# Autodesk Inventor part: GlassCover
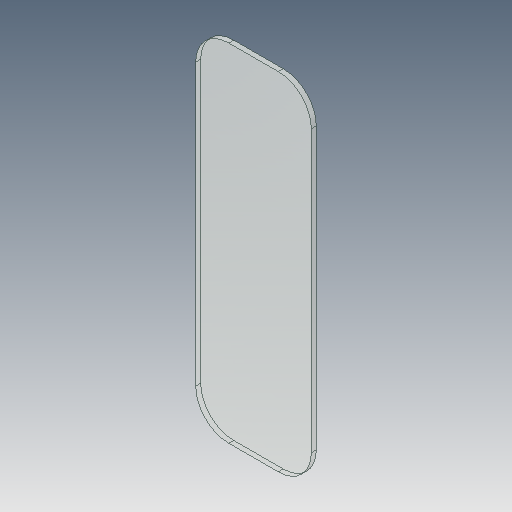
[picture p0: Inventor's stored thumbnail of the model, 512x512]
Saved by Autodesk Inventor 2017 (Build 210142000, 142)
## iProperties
Created: 2019-02
Part Number: GlassCover
Material: Glass
Document SubType Name: Modeling
Designer: user
Density: 2.18 g/cm^3
Appearance: Clear
Mass: 93.8924 g
Surface Area: 302.903 cm^2
Volume: 43.0699 cm^3
Author: user
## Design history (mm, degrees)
sketch "Sketch1"
  geometry: L1 (31.297, 218.537)-(31.297, 50.515) reference; L2 (42.989, 38.823)-(71.011, 38.823) reference; L3 (82.703, 50.515)-(82.703, 218.537) reference; L4 (71.011, 230.23)-(42.989, 230.23) reference; L5 (72, 29.526)-(42, 29.526) reference; L6 (22, 49.526)-(22, 219.526) reference; L7 (42, 239.526)-(72, 239.526) reference; L8 (92, 219.526)-(92, 49.526) reference; A1 r 20 centre (42, 49.526) between (22, 49.526) and (42, 29.526) reference; A2 r 20 centre (42, 219.526) between (42, 239.526) and (22, 219.526) reference; A3 r 20 centre (72, 219.526) between (92, 219.526) and (72, 239.526) reference; A4 r 20 centre (72, 49.526) between (72, 29.526) and (92, 49.526) reference; 1 further point
  constraints: 16 end point, 8 point on circle, 4 centre point, 4 horizontal, 4 vertical, 32 other
extrude "Extrusion1" new body sketch "Sketch1" distance "d0" = 3; taper "d1" = 0 deg
body "Solid1"
